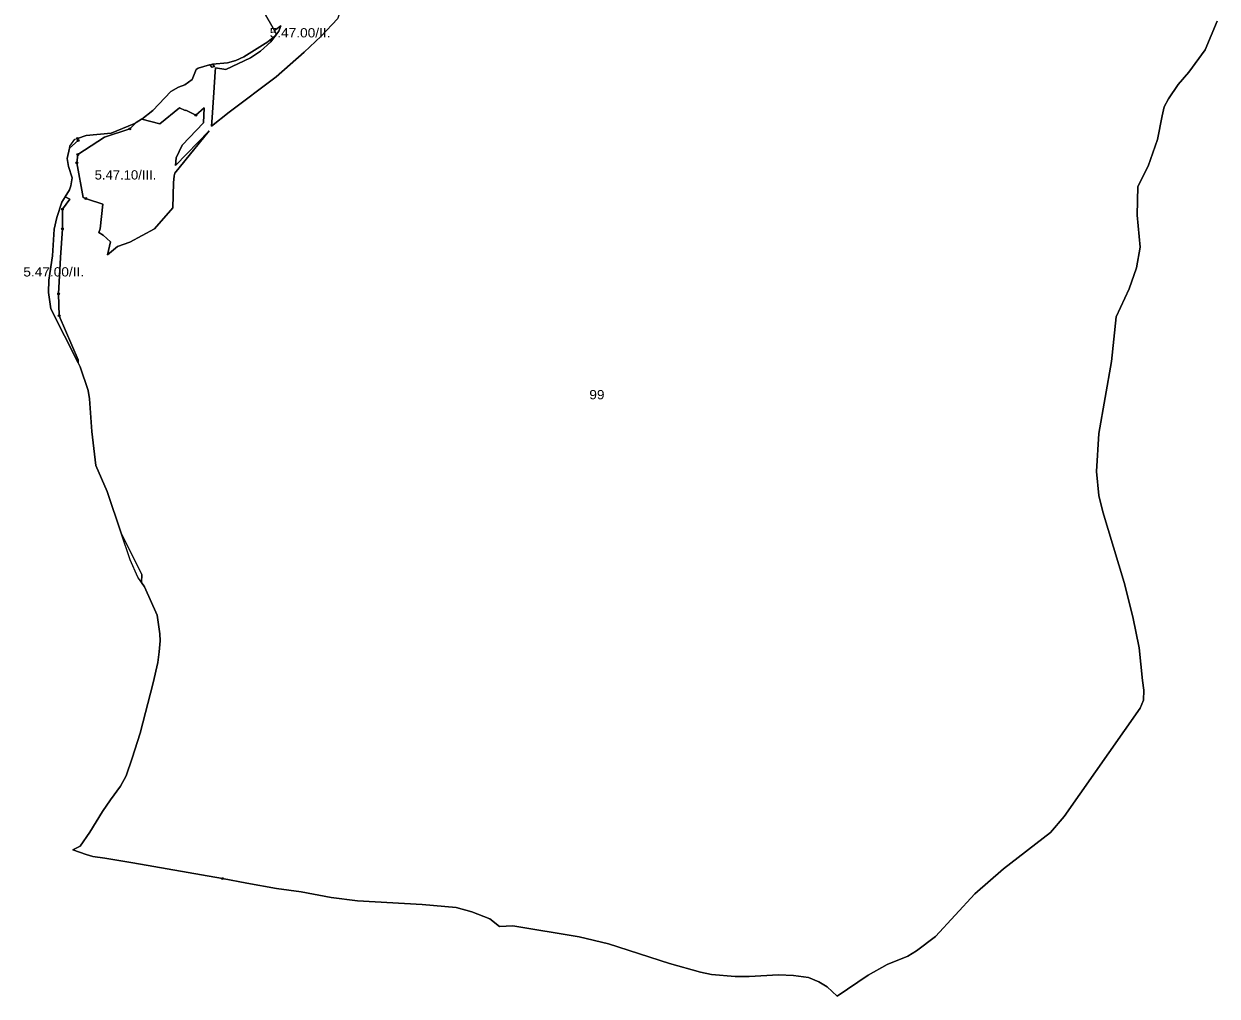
# Model space of a CAD drawing. Extents: x -650455 to -642254, y -1075222 to -1066610.
# Drawn here: x -649050 to -647766, y -1075222 to -1074176 of the extents above; entities that cross this region are included whole.
import ezdxf
from ezdxf.enums import TextEntityAlignment as Align

# ---------------------------------------------------------------- set-up
doc = ezdxf.new("R2010")
doc.units = 0
doc.header["$LTSCALE"] = 4
doc.header["$PDMODE"] = 32
doc.header["$PDSIZE"] = 2
for name, color, linetype, lineweight in [('1', 7, 'Continuous', 25), ('12', 7, 'Continuous', 13), ('13', 7, 'Continuous', 13), ('16', 7, 'Continuous', 13)]:
    doc.layers.add(name, color=color, linetype=linetype, lineweight=lineweight)
doc.layers.add('2', color=7, linetype='Continuous')

msp = doc.modelspace()

# ---------------------------------------------------------------- linework, layer by layer
at = {"layer": '1'}
for points in [[(-648904, -1074283.5), (-648923.613, -1074278.483), (-648911.565, -1074269.193), (-648892.342, -1074248.943), (-648884.125, -1074244.247), (-648877.081, -1074241.752), (-648869.304, -1074236.03), (-648864.902, -1074225.026), (-648862.962, -1074223.588), (-648850.49, -1074220.137), (-648849.67, -1074221.011), (-648848.28, -1074222.49), (-648847.65, -1074222.603), (-648845.34, -1074221.77), (-648847.426, -1074219.41), (-648831.299, -1074217.982), (-648822.495, -1074215.34), (-648813.69, -1074211.526), (-648788.011, -1074195.237), (-648780.234, -1074189.367), (-648778.426, -1074187.092), (-648780.692, -1074183.167), (-648773.97, -1074178.261), (-648775.93, -1074183.911), (-648784.8, -1074195.26), (-648795.65, -1074205.351), (-648806.55, -1074212.621), (-648833.11, -1074225.201), (-648844.05, -1074223.243), (-648844.4, -1074227.801), (-648846.06, -1074249.88), (-648847.75, -1074276.773), (-648848.34, -1074286.15), (-648829.66, -1074270.99), (-648778.97, -1074232.99), (-648748.74, -1074206.61), (-648730.34, -1074189.22), (-648712.77, -1074170.511)], [(-648712.77, -1074170.511), (-648730.34, -1074189.22), (-648748.74, -1074206.61), (-648778.97, -1074232.99), (-648829.66, -1074270.99), (-648848.34, -1074286.15), (-648847.75, -1074276.773), (-648846.06, -1074249.88), (-648844.4, -1074227.801), (-648844.05, -1074223.243), (-648833.11, -1074225.201), (-648806.55, -1074212.621), (-648795.65, -1074205.351), (-648784.8, -1074195.26), (-648775.93, -1074183.911), (-648773.97, -1074178.261), (-648780.692, -1074183.167), (-648793.41, -1074161.141)], [(-647766.475, -1074173.244), (-647779.502, -1074203.89), (-647796.756, -1074227.844), (-647808.375, -1074241.23), (-647818.938, -1074256.729), (-647823.515, -1074265.183), (-647825.694, -1074274.886), (-647830.623, -1074300.601), (-647840.834, -1074329.133), (-647851.749, -1074350.972), (-647852.453, -1074381.971), (-647849.284, -1074416.141), (-647853.157, -1074438.684), (-647861.255, -1074461.228), (-647874.987, -1074491.17), (-647880.268, -1074539.428), (-647893.647, -1074616.572), (-647896.111, -1074657.786), (-647893.647, -1074683.5), (-647889.421, -1074701.114), (-647866.534, -1074776.849), (-647857.027, -1074813.835), (-647850.337, -1074847.3), (-647846.815, -1074882.524), (-647845.221, -1074892.842), (-647845.769, -1074903.457), (-647849.163, -1074912.038), (-647931.068, -1075028.922)], [(-648992, -1074301.501), (-648992.574, -1074299.204), (-648983.32, -1074296.194), (-648956.614, -1074293.698), (-648931.962, -1074283.573), (-648929.699, -1074282.2), (-648936.5, -1074289.001), (-648963.5, -1074298.001), (-648992.5, -1074316.5), (-648993.5, -1074325.501), (-648986.5, -1074363.001), (-648983.669, -1074363.943), (-648983.61, -1074364.28), (-648981.95, -1074364.52), (-648981.933, -1074364.523), (-648965.5, -1074370.001), (-648968.141, -1074396.414), (-648969.59, -1074400.58), (-648965.1, -1074403.2), (-648957.239, -1074410.6), (-648960.37, -1074424.701), (-648949.75, -1074415.441), (-648949.67, -1074415.391), (-648936.5, -1074411.001), (-648910, -1074396.5), (-648890, -1074374.001), (-648889.5, -1074347.001), (-648888.69, -1074339.711), (-648888.06, -1074336.58), (-648851.16, -1074291.13), (-648887.42, -1074328.31), (-648886.5, -1074320), (-648880, -1074306.501), (-648857, -1074282.501), (-648856.5, -1074266.5), (-648865.35, -1074274.371), (-648876.21, -1074268.73), (-648876.892, -1074269.292), (-648883, -1074266.5), (-648904, -1074283.5)], [(-648989.955, -1075060.702), (-648979.565, -1075045.589), (-648965.931, -1075023.453), (-648957.308, -1075010.734), (-648946.461, -1074996.229), (-648940.313, -1074984.954), (-648933.709, -1074966.044), (-648925.17, -1074939.163), (-648911.393, -1074884.942), (-648906.383, -1074863.072), (-648904.675, -1074851.568), (-648903.878, -1074839.721), (-648904.22, -1074832.09), (-648907.066, -1074812.269), (-648920.534, -1074781.84), (-648923.788, -1074777), (-648923.5, -1074768.5), (-648945.63, -1074723.877), (-648960.635, -1074678.95), (-648972.901, -1074651.007), (-648977.157, -1074614.616), (-648979.652, -1074579.398), (-648981.119, -1074570.595), (-648989.776, -1074545.061), (-648991.916, -1074540.822), (-648992, -1074537.501), (-649012.5, -1074490), (-649013, -1074466.5), (-649011, -1074427.501), (-649009, -1074396.5), (-649009, -1074375.501), (-649001, -1074364.5), (-649006.103, -1074362.204), (-649001.369, -1074354.595), (-648999.754, -1074350.193), (-648998.581, -1074341.683), (-649002.396, -1074329.357), (-649003.716, -1074320.845), (-649001.227, -1074309.642), (-648992, -1074301.501)], [(-647931.068, -1075028.922), (-647945.678, -1075045.792), (-647996.448, -1075084.953), (-648027.007, -1075112.056), (-648069.62, -1075157.855), (-648089.831, -1075173.202), (-648099.449, -1075178.988), (-648121.364, -1075187.881), (-648141.818, -1075199.391), (-648175.178, -1075221.987), (-648186.014, -1075211.998), (-648195.024, -1075206.699), (-648206.103, -1075201.949), (-648222.174, -1075199.878), (-648238.61, -1075198.965), (-648270.144, -1075200.731), (-648284.998, -1075200.731), (-648310.566, -1075198.843), (-648322.375, -1075196.285), (-648355.735, -1075186.967), (-648421.237, -1075165.894), (-648452.77, -1075158.16), (-648524.116, -1075146.406), (-648538.604, -1075147.014), (-648548.953, -1075138.853), (-648568.311, -1075131.241), (-648585.113, -1075126.733), (-648621.691, -1075123.255), (-648691.575, -1075119.357), (-648719.699, -1075115.764), (-648751.963, -1075109.736), (-648778.505, -1075106.143), (-648810.561, -1075100.367), (-648836.816, -1075095.565), (-648933.142, -1075078.591), (-648963.202, -1075073.729), (-648976.238, -1075071.7), (-648983.525, -1075069.593), (-648997.809, -1075064.448), (-648989.955, -1075060.702)]]:
    msp.add_lwpolyline(points, dxfattribs=at)
for points in [[(-648845.34, -1074221.77), (-648847.65, -1074222.603), (-648848.28, -1074222.49), (-648849.67, -1074221.011), (-648850.49, -1074220.137), (-648848.07, -1074219.467), (-648847.426, -1074219.41)], [(-648929.699, -1074282.2), (-648923.744, -1074278.584), (-648923.613, -1074278.483), (-648904, -1074283.5), (-648883, -1074266.5), (-648876.892, -1074269.292), (-648876.21, -1074268.73), (-648865.35, -1074274.371), (-648856.5, -1074266.5), (-648857, -1074282.501), (-648880, -1074306.501), (-648886.5, -1074320), (-648887.42, -1074328.31), (-648851.16, -1074291.13), (-648888.06, -1074336.58), (-648888.69, -1074339.711), (-648889.5, -1074347.001), (-648890, -1074374.001), (-648910, -1074396.5), (-648936.5, -1074411.001), (-648949.67, -1074415.391), (-648949.75, -1074415.441), (-648960.37, -1074424.701), (-648957.239, -1074410.6), (-648965.1, -1074403.2), (-648969.59, -1074400.58), (-648968.141, -1074396.414), (-648965.5, -1074370.001), (-648981.933, -1074364.523), (-648981.95, -1074364.52), (-648983.61, -1074364.28), (-648983.669, -1074363.943), (-648986.5, -1074363.001), (-648993.5, -1074325.501), (-648992.5, -1074316.5), (-648963.5, -1074298.001), (-648936.5, -1074289.001)], [(-648992, -1074301.501), (-649001.227, -1074309.642), (-649000.782, -1074307.639), (-648995.499, -1074300.156), (-648992.574, -1074299.204)], [(-648992, -1074537.501), (-648991.916, -1074540.822), (-649021.325, -1074482.551), (-649023.82, -1074464.943), (-649023.673, -1074451.736), (-649019.711, -1074425.617), (-649017.657, -1074396.855), (-649015.016, -1074384.529), (-649009.586, -1074367.802), (-649006.103, -1074362.204), (-649001, -1074364.5), (-649009, -1074375.501), (-649009, -1074396.5), (-649011, -1074427.501), (-649013, -1074466.5), (-649012.5, -1074490)], [(-648923.5, -1074768.5), (-648923.788, -1074777), (-648927.751, -1074771.104), (-648935.982, -1074752.766), (-648945.63, -1074723.877)]]:
    msp.add_lwpolyline(points, close=True, dxfattribs=at)
at = {"layer": '12'}
for points in [[(-648793.41, -1074161.141), (-648780.692, -1074183.167), (-648773.97, -1074178.261), (-648775.93, -1074183.911), (-648784.8, -1074195.26), (-648795.65, -1074205.351), (-648806.55, -1074212.621), (-648833.11, -1074225.201), (-648844.05, -1074223.243), (-648844.4, -1074227.801), (-648846.06, -1074249.88), (-648847.75, -1074276.773), (-648848.34, -1074286.15), (-648829.66, -1074270.99), (-648778.97, -1074232.99), (-648748.74, -1074206.61), (-648730.34, -1074189.22), (-648712.77, -1074170.511)], [(-649012.5, -1074490), (-649013, -1074466.5), (-649011, -1074427.501), (-649009, -1074396.5), (-649009, -1074375.501), (-649001, -1074364.5), (-649006.103, -1074362.204), (-649009.586, -1074367.802), (-649015.016, -1074384.529), (-649017.657, -1074396.855), (-649019.711, -1074425.617), (-649023.673, -1074451.736), (-649023.82, -1074464.943), (-649021.325, -1074482.551), (-648991.916, -1074540.822)], [(-648991.916, -1074540.822), (-648992, -1074537.501), (-649012.5, -1074490)]]:
    msp.add_lwpolyline(points, dxfattribs=at)
msp.add_point((-649012.5, -1074490), dxfattribs=at)
at = {"layer": '13'}
for points in [[(-648910, -1074396.5), (-648890, -1074374.001), (-648889.5, -1074347.001), (-648888.69, -1074339.711), (-648888.06, -1074336.58), (-648851.16, -1074291.13), (-648887.42, -1074328.31), (-648886.5, -1074320), (-648880, -1074306.501), (-648857, -1074282.501), (-648856.5, -1074266.5), (-648865.35, -1074274.371), (-648876.21, -1074268.73), (-648876.892, -1074269.292), (-648883, -1074266.5), (-648904, -1074283.5), (-648923.613, -1074278.483), (-648923.744, -1074278.584), (-648929.699, -1074282.2), (-648936.5, -1074289.001)], [(-648936.5, -1074289.001), (-648963.5, -1074298.001), (-648992.5, -1074316.5), (-648993.5, -1074325.501), (-648986.5, -1074363.001), (-648983.669, -1074363.943), (-648983.61, -1074364.28), (-648981.95, -1074364.52), (-648981.933, -1074364.523), (-648965.5, -1074370.001), (-648968.141, -1074396.414), (-648969.59, -1074400.58), (-648965.1, -1074403.2), (-648957.239, -1074410.6), (-648960.37, -1074424.701), (-648949.75, -1074415.441), (-648949.67, -1074415.391), (-648936.5, -1074411.001), (-648910, -1074396.5)]]:
    msp.add_lwpolyline(points, dxfattribs=at)
msp.add_point((-648936.5, -1074289.001), dxfattribs=at)
at = {"layer": '16'}
for p, q in [((-648992.574, -1074299.204), (-648992, -1074301.501)), ((-648993.5, -1074325.501), (-648992.5, -1074316.5)), ((-649009, -1074375.501), (-649009, -1074396.5))]:
    msp.add_line(p, q, dxfattribs=at)
for points in [[(-648691.81, -1074097.071), (-648690.92, -1074111.641), (-648693.71, -1074119.171), (-648712.77, -1074170.511), (-648730.34, -1074189.22), (-648748.74, -1074206.61), (-648778.97, -1074232.99), (-648829.66, -1074270.99), (-648848.34, -1074286.15), (-648847.75, -1074276.773), (-648846.06, -1074249.88), (-648844.4, -1074227.801), (-648844.05, -1074223.243), (-648833.11, -1074225.201), (-648806.55, -1074212.621), (-648795.65, -1074205.351), (-648784.8, -1074195.26), (-648778.42, -1074187.097)], [(-647857.027, -1074813.835), (-647866.534, -1074776.849), (-647889.421, -1074701.114), (-647893.647, -1074683.5), (-647896.111, -1074657.786), (-647893.647, -1074616.572), (-647880.268, -1074539.428), (-647874.987, -1074491.17), (-647861.255, -1074461.228), (-647853.157, -1074438.684), (-647849.284, -1074416.141), (-647852.453, -1074381.971), (-647851.749, -1074350.972), (-647840.834, -1074329.133), (-647830.623, -1074300.601), (-647825.694, -1074274.886), (-647823.515, -1074265.183), (-647818.938, -1074256.729), (-647808.375, -1074241.23), (-647796.756, -1074227.844), (-647779.502, -1074203.89), (-647766.475, -1074173.244)], [(-648778.426, -1074187.092), (-648780.234, -1074189.367), (-648788.011, -1074195.237), (-648813.69, -1074211.526), (-648822.495, -1074215.34), (-648831.299, -1074217.982), (-648847.426, -1074219.41), (-648845.34, -1074221.77), (-648847.65, -1074222.603), (-648848.28, -1074222.49), (-648849.67, -1074221.011), (-648850.49, -1074220.137), (-648862.962, -1074223.588), (-648864.902, -1074225.026), (-648869.304, -1074236.03), (-648877.081, -1074241.752), (-648884.125, -1074244.247), (-648892.342, -1074248.943), (-648911.565, -1074269.193), (-648923.613, -1074278.483), (-648904, -1074283.5), (-648883, -1074266.5), (-648876.892, -1074269.292), (-648876.21, -1074268.73), (-648865.35, -1074274.371)], [(-648865.35, -1074274.371), (-648856.5, -1074266.5), (-648857, -1074282.501), (-648880, -1074306.501), (-648886.5, -1074320), (-648887.42, -1074328.31), (-648851.16, -1074291.13), (-648888.06, -1074336.58), (-648888.69, -1074339.711), (-648889.5, -1074347.001), (-648890, -1074374.001), (-648910, -1074396.5), (-648936.5, -1074411.001), (-648949.67, -1074415.391), (-648949.75, -1074415.441), (-648960.37, -1074424.701), (-648957.239, -1074410.6), (-648965.1, -1074403.2), (-648969.59, -1074400.58), (-648968.141, -1074396.414), (-648965.5, -1074370.001), (-648981.933, -1074364.523), (-648981.95, -1074364.52), (-648983.61, -1074364.28), (-648983.669, -1074363.943)], [(-648992.5, -1074316.5), (-648963.5, -1074298.001), (-648936.5, -1074289.001), (-648929.699, -1074282.2), (-648931.962, -1074283.573), (-648956.614, -1074293.698), (-648983.32, -1074296.194), (-648992.574, -1074299.204)], [(-648992, -1074301.501), (-649001.227, -1074309.642), (-649003.716, -1074320.845), (-649002.396, -1074329.357), (-648998.581, -1074341.683), (-648999.754, -1074350.193), (-649001.369, -1074354.595), (-649006.103, -1074362.204), (-649001, -1074364.5), (-649009, -1074375.501)], [(-648983.669, -1074363.943), (-648986.5, -1074363.001), (-648993.5, -1074325.501)], [(-649009, -1074396.5), (-649011, -1074427.501), (-649013, -1074466.5)], [(-649013, -1074466.5), (-649012.5, -1074490), (-648992, -1074537.501), (-648991.916, -1074540.822), (-648989.776, -1074545.061), (-648981.119, -1074570.595), (-648979.652, -1074579.398), (-648977.157, -1074614.616), (-648972.901, -1074651.007), (-648960.635, -1074678.95), (-648945.63, -1074723.877), (-648923.5, -1074768.5), (-648923.788, -1074777), (-648920.534, -1074781.84), (-648907.066, -1074812.269), (-648904.22, -1074832.09), (-648903.878, -1074839.721), (-648904.675, -1074851.568), (-648906.383, -1074863.072), (-648911.393, -1074884.942), (-648925.17, -1074939.163), (-648933.709, -1074966.044), (-648940.313, -1074984.954), (-648946.461, -1074996.229), (-648957.308, -1075010.734), (-648965.931, -1075023.453), (-648979.565, -1075045.589), (-648989.955, -1075060.702), (-648997.809, -1075064.448), (-648983.525, -1075069.593), (-648976.238, -1075071.7), (-648963.202, -1075073.729), (-648933.142, -1075078.591), (-648836.816, -1075095.565)], [(-648836.816, -1075095.565), (-648810.561, -1075100.367), (-648778.505, -1075106.143), (-648751.963, -1075109.736), (-648719.699, -1075115.764), (-648691.575, -1075119.357), (-648621.691, -1075123.255), (-648585.113, -1075126.733), (-648568.311, -1075131.241), (-648548.953, -1075138.853), (-648538.604, -1075147.014), (-648524.116, -1075146.406), (-648452.77, -1075158.16), (-648421.237, -1075165.894), (-648355.735, -1075186.967), (-648322.375, -1075196.285), (-648310.566, -1075198.843), (-648284.998, -1075200.731), (-648270.144, -1075200.731), (-648238.61, -1075198.965), (-648222.174, -1075199.878), (-648206.103, -1075201.949), (-648195.024, -1075206.699), (-648186.014, -1075211.998), (-648175.178, -1075221.987), (-648141.818, -1075199.391), (-648121.364, -1075187.881), (-648099.449, -1075178.988), (-648089.831, -1075173.202), (-648069.62, -1075157.855), (-648027.007, -1075112.056), (-647996.448, -1075084.953), (-647945.678, -1075045.792), (-647931.068, -1075028.922), (-647849.163, -1074912.038), (-647845.769, -1074903.457), (-647845.221, -1074892.842), (-647846.815, -1074882.524), (-647850.337, -1074847.3), (-647857.027, -1074813.835)]]:
    msp.add_lwpolyline(points, dxfattribs=at)
for p in [(-648865.35, -1074274.371), (-648992.574, -1074299.204), (-648992, -1074301.501), (-648993.5, -1074325.501), (-648992.5, -1074316.5), (-648983.669, -1074363.943), (-649009, -1074375.501), (-649009, -1074396.5), (-649013, -1074466.5), (-648836.816, -1075095.565)]:
    msp.add_point(p, dxfattribs=at)

# ---------------------------------------------------------------- texts
at = {"layer": '2'}
for s, width, p in [('5.47.00/II.', 1.1, (-648753.213, -1074190.644)), ('5.47.10/III.', 1.05, (-648941.034, -1074343.51)), ('5.47.00/II.', 1.1, (-649018.278, -1074447.826)), ('99', 1.1, (-648433.836, -1074579.942))]:
    msp.add_text(s, height=10, dxfattribs=dict(at, width=width)).set_placement(p, align=Align.CENTER)

doc.saveas('drawing.dxf')
